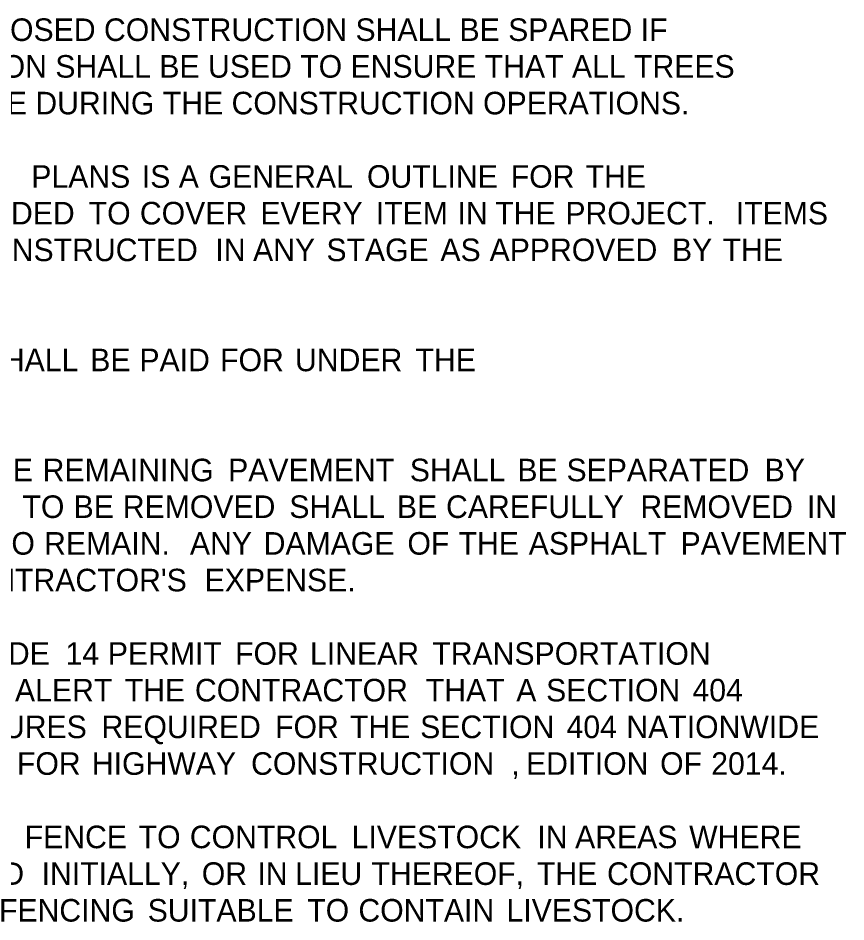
# Model space of a CAD drawing. Extents: x -1197 to 1681, y -1031 to 1021.
# Drawn here: x 919.6 to 1359.7, y 16.5 to 496.8 of the extents above; entities that cross this region are included whole.
import ezdxf

# ---------------------------------------------------------------- set-up
doc = ezdxf.new("R2010")
doc.units = 0
doc.layers.add('Default', color=7, linetype='Continuous')

msp = doc.modelspace()

# ---------------------------------------------------------------- texts
at = {"layer": 'Default'}
for s, p in [('ALL TREES THAT DO NOT DIRECTLY INTERFERE WITH THE PROPOSED CONSTRUCTION SHALL BE SPARED IF', (404.45, 484.66)), ('AND WHERE DIRECTED BY THE ENGINEER. CARE AND DISCRETION SHALL BE USED TO ENSURE THAT ALL TREES  ', (404.45, 465.16)), ('NOT TO BE REMOVED SHALL BE HARMED AS LITTLE AS POSSIBLE DURING THE CONSTRUCTION OPERATIONS.', (404.45, 445.66)), (' PLANS', (922.17, 406.66)), (' IS', (980.94, 406.66)), (' A', (1000.56, 406.66)), (' GENERAL', (1016.43, 406.66)), (' OUTLINE', (1100.63, 406.66)), (' FOR', (1177.06, 406.66)), (' THE', (1216.88, 406.66)), (' INTENDED', (863.22, 387.16)), (' TO', (952.69, 387.16)), (' COVER', (979.88, 387.16)), (' EVERY', (1043.94, 387.16)), (' ITEM', (1105.32, 387.16)), (' IN', (1148.77, 387.16)), (' THE', (1168.81, 387.16)), (' PROJECT.', (1206.11, 387.16)), ('  ITEMS', (1292.23, 387.16)), (' CONSTRUCTED', (887.68, 367.66)), (' IN', (1020, 367.66)), (' ANY', (1040.05, 367.66)), (' STAGE', (1079.06, 367.66)), (' AS', (1139.66, 367.66)), (' APPROVED', (1165.81, 367.66)), (' BY', (1262.77, 367.66)), (' THE', (1289.66, 367.66)), (' SHALL', (896.33, 309.16)), (' BE', (953.51, 309.16)), (' PAID', (979.64, 309.16)), (' FOR', (1022.54, 309.16)), (' UNDER', (1062.36, 309.16)), (' THE', (1126.41, 309.16)), (' THE', (890.89, 250.66)), (' REMAINING', (928.19, 250.66)), (' PAVEMENT', (1026.82, 250.66)), (' SHALL', (1123.38, 250.66)), (' BE', (1180.57, 250.66)), (' SEPARATED', (1206.7, 250.66)), (' BY', (1312.04, 250.66)), (' TO', (917.48, 231.16)), (' BE', (944.67, 231.16)), (' REMOVED', (970.81, 231.16)), (' SHALL', (1059.35, 231.16)), (' BE', (1116.53, 231.16)), (' CAREFULLY', (1142.66, 231.16)), (' REMOVED', (1245.96, 231.16)), (' IN', (1334.51, 231.16)), (' TO', (901.78, 211.66)), (' REMAIN.', (928.97, 211.66)), ('  ANY', (1002.03, 211.66)), (' DAMAGE', (1045.7, 211.66)), (' OF', (1122.13, 211.66)), (' THE', (1149.31, 211.66)), (' ASPHALT', (1186.6, 211.66)), (' PAVEMENT', (1267.34, 211.66)), (" CONTRACTOR'S", (877.85, 192.16)), (' EXPENSE.', (1014.32, 192.16)), (' NATIONWIDE', (829.49, 153.16)), (' 14', (940.37, 153.16)), (' PERMIT', (962.85, 153.16)), (' FOR', (1030.51, 153.16)), (' LINEAR', (1070.34, 153.16)), (' TRANSPORTATION', (1135.33, 153.16)), (' ALERT', (913.49, 133.66)), (' THE', (971.85, 133.66)), (' CONTRACTOR', (1009.15, 133.66)), (' THAT', (1131.88, 133.66)), (' A', (1179.98, 133.66)), (' SECTION', (1195.85, 133.66)), (' 404', (1273.67, 133.66)), (' MEASURES', (861.61, 114.16)), (' REQUIRED', (959.5, 114.16)), (' FOR', (1051.77, 114.16)), (' THE', (1091.59, 114.16)), (' SECTION', (1128.89, 114.16)), (' 404', (1206.71, 114.16)), (' NATIONWIDE', (1238.51, 114.16)), (' FOR', (914.54, 94.66)), (' HIGHWAY', (954.36, 94.66)), (' CONSTRUCTION', (1039, 94.66)), (' EDITION', (1185.18, 94.66)), (' OF', (1256.46, 94.66)), (' 2014.', (1283.64, 94.66)), (' ,', (1177.36, 94.66)), (' FENCE', (918.65, 55.66)), (' TO', (979.25, 55.66)), (' CONTROL', (1006.44, 55.66)), (' LIVESTOCK', (1092.48, 55.66)), (' IN', (1191.21, 55.66)), (' AREAS', (1211.26, 55.66)), (' WHERE', (1271.89, 55.66)), (' CONSTRUCTED', (795.33, 36.16)), (' INITIALLY,', (927.65, 36.16)), (' OR', (1012.81, 36.16)), (' IN', (1042.38, 36.16)), (' LIEU', (1062.43, 36.16)), (' THEREOF,', (1103.01, 36.16)), (' THE', (1190.95, 36.16)), (' CONTRACTOR', (1228.25, 36.16)), (' FENCING', (904.98, 16.66)), (' SUITABLE', (984.04, 16.66)), (' TO', (1068.87, 16.66)), (' CONTAIN', (1096.06, 16.66)), (' LIVESTOCK.', (1174.81, 16.66))]:
    msp.add_text(s, height=12, dxfattribs=at).set_placement(p)

doc.saveas('drawing.dxf')
